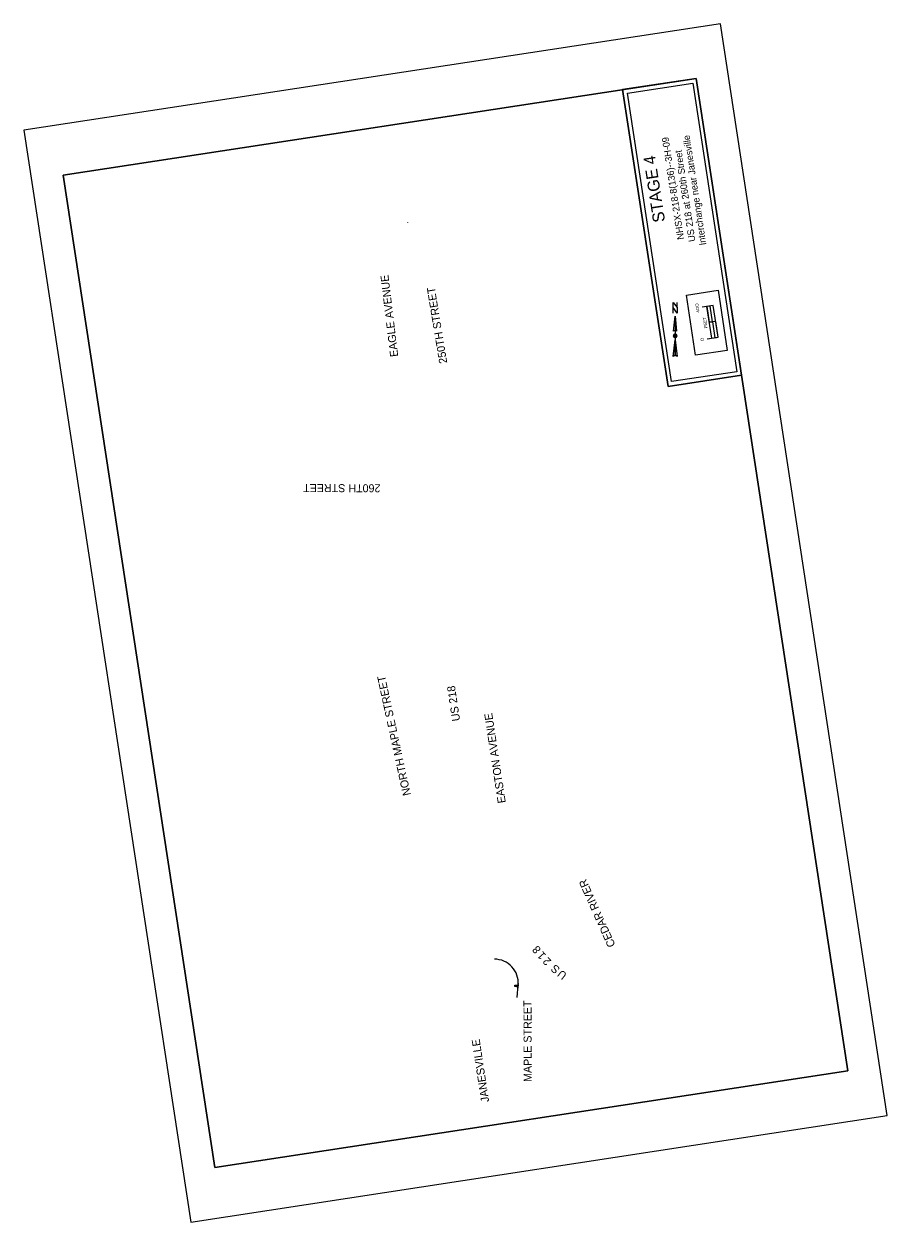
# Model space of a CAD drawing. Extents: x 5192026 to 5202808, y 3700291 to 3715256.
import ezdxf

# ---------------------------------------------------------------- set-up
doc = ezdxf.new("R2010")
doc.units = 0
for name, color, linetype in [('_CIVIL_CONSTRUCTION', 7, 'Continuous'), ('CorridorGraphics', 7, 'Continuous'), ('TC_CurbGutter', 7, 'Continuous'), ('TC_Grading', 7, 'Continuous'), ('TC_PCCPavement', 7, 'Continuous'), ('TL_PavementTop', 7, 'Continuous'), ('TL_Subbase', 7, 'Continuous'), ('TL_SubbaseBtm', 7, 'Continuous')]:
    doc.layers.add(name, color=color, linetype=linetype)

msp = doc.modelspace()

# ---------------------------------------------------------------- linework, layer by layer
at = {"layer": '_CIVIL_CONSTRUCTION'}
for points in [[(5200072, 3710728), (5199505, 3714435), (5200425, 3714575), (5200991, 3710868)], [(5200116, 3710788), (5199566, 3714391), (5200381, 3714515), (5200931, 3710912)]]:
    msp.add_lwpolyline(points, close=True, dxfattribs=at)
for points in [[(5200991, 3710868), (5200425, 3714575), (5199505, 3714435), (5200072, 3710728), (5200991, 3710868)], [(5200116, 3710788), (5199566, 3714391), (5200381, 3714515), (5200931, 3710912), (5200116, 3710788)]]:
    msp.add_lwpolyline(points, dxfattribs=at)
at = {"layer": 'CorridorGraphics'}
msp.add_line((5200668, 3711541), (5200588, 3711529), dxfattribs=at)
msp.add_line((5200668, 3711541), (5200588, 3711529), dxfattribs=at)
for points in [[(5200416, 3711118), (5200302, 3711869), (5200697, 3711930), (5200812, 3711178)], [(5200812, 3711178), (5200416, 3711118), (5200302, 3711869), (5200697, 3711930)], [(5200628, 3711535), (5200597, 3711732), (5200558, 3711726), (5200588, 3711529)], [(5200698, 3711343), (5200668, 3711541), (5200628, 3711535), (5200658, 3711337)]]:
    msp.add_lwpolyline(points, close=True, dxfattribs=at)
for points in [[(5200559, 3711322), (5200698, 3711343), (5200637, 3711739), (5200499, 3711717)], [(5200619, 3711331), (5200558, 3711726)]]:
    msp.add_lwpolyline(points, dxfattribs=at)
at = {"layer": 'TC_CurbGutter'}
for p, q in [((5198158, 3703248), (5198186, 3703250)), ((5198158, 3703248), (5198186, 3703250)), ((5198159, 3703231), (5198158, 3703248)), ((5198159, 3703231), (5198158, 3703248)), ((5198186, 3703094), (5198200, 3703254)), ((5198186, 3703094), (5198200, 3703254)), ((5198197, 3703220), (5198200, 3703257)), ((5198200, 3703257), (5198197, 3703220)), ((5198182, 3703229), (5198159, 3703231))]:
    msp.add_line(p, q, dxfattribs=at)
for centre, radius, start, end in [((5197906, 3703279), 295, 355.0831, 90.5978), ((5198185, 3703270), 20, 272.8175, 358.0701), ((5198185, 3703270), 20, 272.8175, 358.0701), ((5198180, 3703209), 20, 355.0839, 84.4202)]:
    msp.add_arc(centre, radius, start, end, dxfattribs=at)
at = {"layer": 'TC_Grading'}
for q in [(5196823, 3712774), (5196823, 3712770)]:
    msp.add_line((5196823, 3712770), q, dxfattribs=at)
at = {"layer": 'TL_PavementTop'}
for p, q in [((5200161, 3711607), (5200180, 3711417)), ((5200161, 3711607), (5200161, 3711113)), ((5200142, 3711419), (5200146, 3711423)), ((5200142, 3711417), (5200142, 3711417)), ((5200161, 3711336), (5200161, 3711336)), ((5200137, 3711103), (5200161, 3711312))]:
    msp.add_line(p, q, dxfattribs=at)
msp.add_lwpolyline([(5200185, 3711645), (5200137, 3711712), (5200137, 3711778), (5200185, 3711712)], close=True, dxfattribs=at)
for points in [[(5200137, 3711645), (5200137, 3711778), (5200185, 3711712), (5200185, 3711778)], [(5200142, 3711417), (5200161, 3711607), (5200161, 3711426)], [(5200161, 3711336), (5200161, 3711360), (5200137, 3711360)], [(5200185, 3711360), (5200161, 3711360), (5200161, 3711384)], [(5200161, 3711113), (5200161, 3711312), (5200185, 3711103)]]:
    msp.add_lwpolyline(points, dxfattribs=at)
for centre, radius, start, end in [((5200161, 3711360), 23.8, 90, 180), ((5200161, 3711360), 23.8, 180, 270), ((5200161, 3711403), 23.8, 90.0204, 143.1257), ((5200161, 3711403), 23.8, 36.8481, 90.0218), ((5200161, 3711360), 23.8, 0, 90), ((5200161, 3711360), 23.8, 270, 360), ((5200161, 3711078), 34.4, 89.9894, 133.619), ((5200161, 3711078), 34.5, 46.4021, 90.0006)]:
    msp.add_arc(centre, radius, start, end, dxfattribs=at)
at = {"layer": 'TL_Subbase'}
for points in [[(5194109, 3700291), (5202808, 3701620), (5200726, 3715256), (5192026, 3713927)], [(5194410, 3700971), (5202318, 3702179), (5200425, 3714575), (5192516, 3713368)]]:
    msp.add_lwpolyline(points, close=True, dxfattribs=at)
at = {"layer": 'TL_SubbaseBtm'}
msp.add_lwpolyline([(5194410, 3700971), (5192516, 3713368), (5200425, 3714575), (5202318, 3702179)], close=True, dxfattribs=at)

# ---------------------------------------------------------------- texts
at = {"layer": 'CorridorGraphics'}
for s, height, p in [('NHSX-218-8(136)--3H-09', 85, (5200273, 3712568)), ('Interchange near Janesville', 85, (5200551, 3712498)), ('  US 218 at 260th Street ', 85, (5200425, 3712479)), ('4OO', 40, (5200468, 3711653)), ('FEET', 40, (5200567, 3711457)), ('O', 40, (5200523, 3711296)), ('O', 40, (5200523, 3711296))]:
    msp.add_text(s, height=height, rotation=98.6831, dxfattribs=at).set_placement(p)
at = {"layer": 'TC_PCCPavement'}
msp.add_text('STAGE 4', height=148.9, rotation=98.6831, dxfattribs=at).set_placement((5200036, 3712789))
at = {"layer": 'TL_SubbaseBtm'}
for s, rotation, p in [('EAGLE AVENUE', 96.8932, (5196702, 3711103)), ('250TH STREET', 99.3981, (5197315, 3711022)), ('260TH STREET', 179.8345, (5196480, 3709506)), ('NORTH MAPLE STREET', 102.2339, (5196860, 3705628)), ('US 218', 98.6831, (5197476, 3706555)), ('EASTON AVENUE', 98.6831, (5198046, 3705530)), ('CEDAR RIVER', 114.0562, (5199418, 3703750)), ('8', 129.328, (5198491, 3703695)), ('1', 131.4754, (5198554, 3703624)), ('2', 134.1916, (5198621, 3703555)), ('S', 139.0446, (5198730, 3703458)), ('U', 141.745, (5198817, 3703388)), ('MAPLE STREET', 90.1417, (5198369, 3702041)), ('JANESVILLE', 98.6831, (5197838, 3701796))]:
    msp.add_text(s, height=100, rotation=rotation, dxfattribs=at).set_placement(p)

doc.saveas('drawing.dxf')
